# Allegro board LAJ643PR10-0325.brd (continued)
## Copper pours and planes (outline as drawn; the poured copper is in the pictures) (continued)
NVVDD_LG1 on IN3 (solid shape): 225.57,54.58 226.25,54.58 226.79,54.04 226.79,52.64 226.55,52.4 226.11,52.4 225.98,52.52 225.98,52.78 226.17,52.97 226.17,53.6 225.94,53.82 225.6,53.82 225.56,53.86 225.56,54.59
NVVDD_LG1 on IN3: 207.67,59.04 207.03,59.04 206.86,58.87 206.86,58.24 207.83,57.27 208.06,57.27 208.58,57.79 208.58,58.13
NVVDD_LG2 on BOTTOM (solid shape): 199.65,59.9 199.65,57.9 199.57,57.81 199.12,57.81 199.11,57.82 198.49,57.82 198.45,57.86 198.45,59.48 198.46,59.49 198.46,59.98 198.6,60.11 199.44,60.11
NVVDD_LG2 on BOTTOM (solid shape): 227.99,54.33 227.99,53.64 228.62,53.01 228.62,52.8 228.54,52.71 228.33,52.71 228.28,52.77 227.83,52.77 227.72,52.89 227.72,53.54 227.77,53.59 227.77,54.35 227.82,54.4 227.92,54.4
NVVDD_LG2 on IN1 (solid shape): 228.63,53.01 228.63,52.8 228.53,52.7 228.1,52.7 227.49,52.09 227.44,52.09 226.95,52.58 226.95,52.65 227.74,53.44 228.2,53.44
NVVDD_LG2 on IN1: 199.37,58.91 198.94,58.49 198.94,58.15 199.76,57.34 200.09,57.34 200.62,57.87 200.62,57.99 199.69,58.91
NVVDD_LG3 on BOTTOM (solid shape): 219.97,60.83 219.98,60.83 220.11,60.7 220.11,59.5 220.04,59.43 219.93,59.43 219.85,59.51 219.85,60.15 219.63,60.37 218.55,60.37 218.41,60.24 217.49,60.24 216,58.75 215.2,58.75 215.09,58.64 215.09,58.22 214.97,58.1 214.38,58.1 214.32,58.16 214.32,59.86 214.35,59.88 216.05,59.88 217.04,60.88 219.93,60.88
NVVDD_LX1 on BOTTOM (solid shape): 206.05,54.29 206.05,53.18 206.01,53.15 205.16,53.15 205.12,53.18 205.12,54.32 205.16,54.36 205.98,54.36
NVVDD_LX1 on BOTTOM (solid shape): 226,54.34 226,53.62 225.89,53.51 225.89,53.23 225.51,52.85 225.51,52.4 225.46,52.35 224.95,52.35 224.88,52.42 224.88,53.56 225.72,54.4 225.94,54.4
NVVDD_LX1 on IN3 (solid shape): 206.96,53.79 206.96,52.91 206.81,52.76 205.32,52.76 205.17,52.91 205.17,53.77 205.32,53.91 206.85,53.91
NVVDD_LX1 on IN3 (solid shape): 225.95,53.24 225.95,53.18 224.78,52.01 224.63,52.01 224.23,52.41 224.23,52.6 224.48,52.85 224.48,52.86 225.14,53.51 225.67,53.51
NVVDD_LX1_1 on BOTTOM (solid shape): 207.26,63.23 207.26,61.13 207.12,60.98 206,60.98 205.79,60.77 205.79,59.29 205.72,59.22 202.55,59.22 202.5,59.28 202.5,63.21 202.6,63.32 204.38,63.32 204.39,63.3 204.43,63.26 204.43,62.42 204.47,62.39 205.24,62.39 205.3,62.44 205.3,63.24 205.38,63.32 207.17,63.32
NVVDD_LX2 on BOTTOM (solid shape): 197.99,54.25 197.99,53.14 197.95,53.11 197.1,53.11 197.06,53.14 197.06,54.28 197.1,54.32 197.92,54.32
NVVDD_LX2 on BOTTOM (solid shape): 228.51,54.3 228.51,53.91 228.99,53.44 229.3,53.44 229.87,54 230.71,54 231.14,53.57 231.14,53.26 231.01,53.13 230.15,53.13 230.01,52.99 230.01,52.48 229.92,52.4 229.51,52.4 228.28,53.62 228.28,54.32 228.34,54.38 228.43,54.38
NVVDD_LX2 on IN1 (solid shape): 198.93,53.54 198.93,52.91 198.8,52.78 197.09,52.78 196.94,52.93 196.94,53.47 197.07,53.6 197.86,53.6 197.88,53.62 198.85,53.62
NVVDD_LX2 on IN1 (solid shape): 231.7,53.13 231.7,52.25 231.53,52.07 230.97,52.07 230.89,52.14 230.89,52.86 230.33,53.41 230.33,53.95 230.51,54.13 230.71,54.13
NVVDD_LX2_1 on BOTTOM (solid shape): 196.74,63.29 196.74,62.42 196.8,62.36 197.56,62.36 197.62,62.43 197.62,63.25 197.7,63.33 199.35,63.33 199.54,63.14 199.54,61.44 199.11,61.01 198.05,61.01 197.87,60.83 197.87,59.27 197.79,59.19 194.58,59.19 194.53,59.25 194.53,63.02 194.84,63.34 196.7,63.34
NVVDD_LX3 on BOTTOM (solid shape): 213.86,54.29 213.86,53.19 213.83,53.15 212.98,53.15 212.94,53.19 212.94,54.33 212.97,54.36 213.8,54.36
NVVDD_LX3 on BOTTOM (solid shape): 220.1,58 220.1,57.31 220.32,57.09 220.71,57.09 220.85,57.23 221.11,57.23 221.63,56.71 221.63,56.08 221.57,56.02 220.94,56.02 220.86,56.1 220.86,56.38 220.82,56.42 220.29,56.42 220.21,56.49 220.21,56.69 219.86,57.04 219.86,57.99 219.93,58.05 220.05,58.05
NVVDD_LX3_1 on BOTTOM (solid shape): 213.37,63.33 214.29,63.33 214.29,63.33 214.9,63.33 215.13,63.1 215.13,61.59 215.12,61.49 215.13,61.39 215.13,60.87 214.65,60.39 214.14,60.39 214.11,60.37 214.1,60.37 213.9,60.16 213.9,60.15 213.82,60.07 213.82,59.22 210.63,59.22 210.54,59.31 210.54,63.22 210.66,63.33 212.11,63.33 212.2,63.24 212.2,62.41 212.96,62.41 213.03,62.48 213.03,63.35 213.36,63.35
NVVDD_UG1 on BOTTOM (solid shape): 210.04,54.43 210.04,53.12 209.96,53.05 209.14,53.05 209.08,53.11 209.08,54.44 209.13,54.49 209.97,54.49
NVVDD_UG1 on BOTTOM (solid shape): 225.45,55.36 225.45,55.21 225.41,55.17 224.75,55.17 224.18,54.61 224.18,54.51 224,54.32 223.83,54.32 223.69,54.45 223.69,55.06 223.81,55.17 224.17,55.17 224.41,55.41 225.4,55.41
NVVDD_UG1 on IN3 (solid shape): 210.81,53.35 210.81,52.75 210.74,52.68 209.15,52.68 209.02,52.8 209.02,53.32 209.16,53.47 210.69,53.47
NVVDD_UG1 on IN3 (solid shape): 224.54,55.05 224.54,54.89 223.78,54.13 223.49,54.13 223.26,53.91 223.16,53.91 222.75,54.32 222.75,54.55 223.33,55.13 224.1,55.13 224.18,55.2 224.39,55.2
NVVDD_UG1_R on BOTTOM (solid shape): 208.46,54.52 208.46,53.64 208.43,53.62 206.55,53.62 206.41,53.75 206.41,54.3 206.46,54.35 207.6,54.35 207.77,54.53 208.45,54.53
NVVDD_UG2 on BOTTOM (solid shape): 202.17,54.35 202.17,53.1 202.09,53.03 201.27,53.03 201.21,53.09 201.21,54.18 201.21,54.18 201.21,54.42 201.27,54.48 202.04,54.48
NVVDD_UG2 on IN1 (solid shape): 202.19,53.39 202.19,52.01 202.19,52.02 202.19,52.04 202.12,51.97 201.58,51.97 201.07,52.48 201.07,53.33 201.22,53.48 202.11,53.48
NVVDD_UG2 on IN1 (solid shape): 230.76,55.37 230.76,55.04 230.61,54.89 230.33,54.89 229.85,54.4 229.85,53.87 229.77,53.79 229.16,53.79 229.06,53.9 229.06,54.79 229.77,55.5 230.64,55.5
NVVDD_UG2_R on BOTTOM (solid shape): 200.54,54.44 200.54,53.6 200.51,53.57 198.6,53.57 198.46,53.71 198.46,54.26 198.51,54.31 199.65,54.31 199.82,54.48 200.49,54.48
NVVDD_UG3_R on BOTTOM (solid shape): 216.37,54.22 216.37,53.38 216.35,53.36 215.79,53.36 215.52,53.63 214.51,53.63 214.38,53.77 214.38,54.32 214.43,54.37 216.22,54.37
QPCN on TOP (solid shape): 238.59,15.27 238.59,12.14 238.55,12.1 238.45,12.1 238.4,12.15 238.4,13.32 237.66,14.06 237.66,15.26 237.72,15.33 238.54,15.33
QPCP on TOP (solid shape): 239.86,15.22 239.86,13.97 239.77,13.88 239.48,13.88 238.98,13.39 238.98,12.13 238.95,12.1 238.83,12.1 238.8,12.13 238.8,15.18 238.89,15.28 239.8,15.28
SNB_1.35VSDGPUP on BOTTOM (solid shape): 261.85,59.19 261.85,58.51 261.6,58.25 260.92,58.25 260.49,57.82 259,57.82 258.89,57.93 258.89,59.24 258.99,59.34 261.71,59.34
SNB_PH1 on TOP (solid shape): 149.69,126.45 149.69,124.8 149.62,124.74 147.72,124.74 147.66,124.8 147.66,125.44 147.75,125.53 148.44,125.53 148.61,125.7 148.61,126.45 148.67,126.52 149.62,126.52
SNB_PH2 on TOP (solid shape): 143,126.58 144.61,126.58 144.67,126.52 144.67,124.93 144.61,124.86 143.65,124.86 142.38,126.13 142.38,126.26 142.79,126.67 142.91,126.67
SNB_PH3 on BOTTOM (solid shape): 140.54,128.93 140.54,128.36 140.86,128.04 141.43,128.04 141.5,127.98 141.5,126.96 141.37,126.83 139.97,126.83 139.84,126.96 139.84,128.86 139.97,128.99 140.48,128.99
SNB_PH4 on TOP (solid shape): 128.48,129.5 128.48,128.23 128.41,128.17 127.91,128.17 127.87,128.2 127.87,128.7 127.89,128.72 127.89,129.19 127.65,129.44 127.21,129.44 127.14,129.37 127.14,128.74 127.08,128.67 125.43,128.67 125.37,128.74 125.37,129.75 125.56,129.94 128.03,129.94
SPK_L+_CONN on TOP (solid shape): 300.33,45.18 300.33,44.27 298.43,42.37 296.57,42.37 296.45,42.49 296.45,43.25 296.68,43.48 297.21,43.48 297.53,43.48 297.55,43.51 298.13,43.51 299.15,44.53 299.15,45.14 299.46,45.45 300.05,45.45
SPK_L+_CONN on BOTTOM (solid shape): 300.39,44.46 300.22,44.29 299.27,44.29 299.2,44.37 299.2,45.18 299.56,45.54 299.56,46.71 299.58,46.73 300.39,46.73
SPK_L-_CONN on TOP (solid shape): 301.75,44.84 301.75,43.35 298.57,40.17 297.1,40.17 297.04,40.23 297.04,41.35 297.24,41.55 298.44,41.55 300.64,43.75 300.64,44.82 300.8,44.98 301.61,44.98
SPK_L-_CONN on BOTTOM (solid shape): 301.64,45.46 301.74,45.36 301.74,44.36 301.61,44.23 300.87,44.23 300.67,44.43 300.67,45.28 300.82,45.43 300.82,46.73 301.64,46.73
SPK_OUT_L+ on TOP (solid shape): 291.19,21.54 292.36,21.54 292.41,21.49 292.41,21.38 292.36,21.33 291.22,21.33 291.04,21.16 290.3,21.16 290.15,21.31 290.15,21.46 290.3,21.61 291.11,21.61
SPK_OUT_L+ on TOP (solid shape): 292.56,43.49 292.56,42.45 292.44,42.34 290.24,42.34 290.24,42.34 290.17,42.34 290.04,42.48 290.04,43.46 290.19,43.62 292.43,43.62
SPK_OUT_L+ on IN3 (solid shape): 292.98,43.42 292.98,42.62 292.88,42.51 290.68,42.51 290.42,42.77 290.42,43.39 290.62,43.58 292.82,43.58
SPK_OUT_L+ on IN3 (solid shape): 289.13,22.14 289.74,22.14 289.97,21.9 291.31,21.9 291.42,21.79 291.42,21.47 291.21,21.26 290.21,21.26 290.1,21.37 288.39,21.37 288.16,21.6 288.16,22.02 288.28,22.15 289.12,22.15
SPK_OUT_L- on TOP (solid shape): 292.56,41.63 292.56,40.64 292.38,40.46 290.23,40.46 290.04,40.65 290.04,41.58 290.2,41.74 292.45,41.74
SPK_OUT_L- on TOP (solid shape): 292.41,21.08 292.41,20.98 292.37,20.94 291.2,20.94 290.78,20.52 290.02,20.52 289.92,20.62 289.92,20.9 290.05,21.03 291.08,21.03 291.18,21.13 292.36,21.13
SPK_OUT_L- on IN3 (solid shape): 292.87,40.56 292.87,40.46 292.28,39.87 291.66,39.87 290.47,41.06 290.47,41.3 291.09,41.92 291.51,41.92
SPK_OUT_L- on IN3 (solid shape): 288.17,21.23 288.28,21.12 288.58,21.11 288.7,21.12 289.99,21.12 290.11,21.01 291.12,21.01 291.2,20.93 291.2,20.59 291.13,20.51 289.19,20.51 288.92,20.23 287.52,20.23 287.01,20.74 287.01,20.75 287.01,20.99 287.26,21.24 288.15,21.24
SPK_OUT_R+ on TOP (solid shape): 292.56,39.6 292.56,38.61 292.47,38.52 290.66,38.52 290.33,38.85 290.33,39.54 290.56,39.77 292.4,39.77
SPK_OUT_R+ on TOP (solid shape): 292.41,20.29 292.41,20.19 292.36,20.14 291.55,20.14 290.72,19.31 290.72,19.01 290.58,18.87 289.69,18.87 289.59,18.97 289.59,19.43 289.74,19.58 290.68,19.58 291.43,20.33 292.38,20.33
SPK_OUT_R+ on IN3 (solid shape): 290.68,19.36 290.68,18.09 289.82,17.22 288.48,17.22 288.21,17.49 288.21,18.03 289.28,19.1 289.28,19.25 289.51,19.47 290.56,19.47
SPK_OUT_R+ on IN3 (solid shape): 291.6,39.57 291.6,39.2 291.47,39.07 290.65,39.07 289.81,39.92 289.44,39.92 289.34,40.02 289.34,40.92 289.42,41.01 290.16,41.01
SPK_OUT_R- on TOP (solid shape): 289.98,39.53 289.98,38.67 290.74,37.92 292.43,37.92 292.56,37.79 292.56,36.8 292.48,36.72 290.21,36.72 288.78,38.16 288.78,39.59 288.9,39.71 289.8,39.71
SPK_OUT_R- on TOP (solid shape): 292.41,20.67 292.41,20.6 292.36,20.54 291.39,20.54 290.58,19.73 289.79,19.73 289.72,19.81 289.72,20.24 289.82,20.34 290.86,20.34 291.25,20.73 292.35,20.73
SPK_OUT_R- on IN3 (solid shape): 289.91,39.4 289.91,39.11 288.76,37.97 288.64,37.97 288.09,38.52 288.09,38.8 288.87,39.58 289.73,39.58
SPK_OUT_R- on IN3 (solid shape): 290.93,19.98 290.67,19.73 289.4,19.73 288.39,18.71 287.62,18.71 287.62,19.6 287.91,19.88 288.93,19.88 289.3,20.26 290.93,20.26
SPK_R+_CONN on TOP (solid shape): 303.17,44.85 303.17,43.63 302.95,43.42 302.21,43.42 302.07,43.55 302.07,44.83 302.2,44.95 303.07,44.95
SPK_R+_CONN on TOP (solid shape): 300.24,40.04 300.24,39.69 298.85,38.29 297.36,38.29 297.08,38.57 297.08,39.35 297.31,39.57 298.45,39.57 299.49,40.62 299.67,40.62
SPK_R+_CONN on BOTTOM (solid shape): 303.08,46.66 303.08,44.39 302.93,44.25 302.23,44.25 302.06,44.41 302.06,46.63 302.17,46.73 303.01,46.73
SPK_R-_CONN on TOP (solid shape): 304.66,44.79 304.66,43.64 304.5,43.49 303.65,43.49 303.5,43.64 303.5,44.83 303.64,44.97 304.48,44.97
SPK_R-_CONN on TOP (solid shape): 300.39,37.89 300.39,37.62 299.13,36.36 297.25,36.36 297.08,36.52 297.08,37.21 297.29,37.42 298.66,37.42 299.67,38.43 299.85,38.43
SPK_R-_CONN on BOTTOM (solid shape): 304.37,46.63 304.37,45.66 304.56,45.47 304.56,44.52 304.41,44.38 303.55,44.38 303.33,44.6 303.33,46.64 303.42,46.73 304.27,46.73
SPOK# on TOP (solid shape): 17.61,80.54 17.61,78.51 17.48,78.38 17.1,78.38 16.97,78.51 16.97,79.4 16.85,79.53 16.59,79.53 16.46,79.65 16.46,80.54 16.59,80.67 17.48,80.67
UG_DDR on TOP (solid shape): 94.19,33.3 94.19,32.41 94.06,32.28 93.17,32.28 93.05,32.41 93.05,33.17 93.3,33.42 94.06,33.42
N15156561 on BOTTOM (solid shape): 221.1,61.28 221.1,60.73 221.25,60.58 222.48,60.58 222.65,60.41 222.65,59.92 222.55,59.81 220.93,59.81 220.55,59.44 220.45,59.44 220.45,59.44 220.37,59.53 220.37,60.65 220.48,60.76 220.48,61.38 220.51,61.4 220.98,61.4
N17572010 on BOTTOM (solid shape): 240.42,49.72 240.42,48.75 240.38,48.71 238.47,48.71 238.38,48.79 238.38,49.65 238.5,49.77 240.37,49.77
N20648577 on BOTTOM (solid shape): 236.71,26.71 236.71,26.64 236.65,26.58 235.87,26.58 235.84,26.54 235.84,26.38 235.85,26.36 236.65,26.36 236.69,26.32 236.69,26.22 236.63,26.16 236.5,26.16 236.44,26.09 236.43,26.09 236.07,25.74 236.07,24.69 236.26,24.5 236.26,24.03 236.24,24.01 235.25,24.01 235.16,24.1 235.16,26.36 235.57,26.77 235.64,26.81 236.6,26.81
N23332881 on TOP (solid shape): outline of 81 points within 274.07,13.12 276.54,18.85
N23332897 on TOP (solid shape): 272.25,15.31 273.46,15.31 273.55,15.23 273.55,14.69 273.47,14.62 270.82,14.62 270.64,14.79 270.64,15.69 270.74,15.79 271.77,15.79
N23332925 on TOP (solid shape): 276.5,12.3 276.5,10.13 276.25,9.88 274.7,9.88 274.63,9.94 274.63,12.42 274.75,12.55 276.25,12.55
N27740851 on TOP (solid shape): 45.95,43.26 45.95,43.25 46.04,43.17 46.04,39.54 45.98,39.48 45.9,39.48 45.84,39.54 45.84,40.62 45.76,40.69 44.54,40.69 44.44,40.59 44.44,39.53 44.39,39.48 44.25,39.48 44.15,39.58 44.15,40.7 44.21,40.76 44.21,43.05 44.09,43.16 43.05,43.16 42.99,43.22 42.99,43.3 43.05,43.36 43.84,43.36 43.84,43.36 45.85,43.36
N27740851 on BOTTOM (solid shape): 46.06,43.22 46.06,41.01 45.72,40.66 44.46,40.66 44.22,40.9 44.22,43.25 44.35,43.38 45.91,43.38
N27801570 on TOP (solid shape): 44.38,47.43 44.43,47.38 44.43,46.4 44.57,46.26 45.7,46.26 45.85,46.4 45.85,47.37 45.88,47.41 46.01,47.41 46.04,47.37 46.04,46.2 45.95,46.11 45.95,43.6 45.91,43.56 43.03,43.56 42.99,43.6 42.99,43.72 43.03,43.76 44.04,43.76 44.19,43.91 44.19,47.37 44.26,47.44 44.38,47.44
N27801570 on BOTTOM (solid shape): 46.08,46.06 46.08,43.66 45.99,43.57 44.28,43.57 44.18,43.68 44.18,46.1 44.26,46.19 45.96,46.19
N80922351 on BOTTOM (solid shape): 173.74,103.07 173.74,102.66 175.21,101.19 175.21,100.94 173.92,99.64 173.11,99.64 173.01,99.72 172.9,99.76 172.88,99.77 171.3,101.34 171.3,101.85 171.46,102.01 171.47,101.99 171.8,102.32 172.19,101.93 172.22,101.93 172.57,102.28 172.57,102.31 172.19,102.69 172.19,102.71 172.35,102.87 172.39,102.87 172.78,102.49 173.13,102.84 173.13,102.87 172.74,103.26 173.01,103.53 173.28,103.53
N100118189 on TOP (solid shape): 40.07,34.96 40.07,26.22 39.91,26.06 38.44,26.06 38.31,26.19 38.31,35.84 38.44,35.96 39.07,35.96

Small or netless copper shapes (teardrops, artwork), in the pictures only: 140 on TOP, 48 on BOTTOM, 34 on IN2

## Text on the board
User.Comments: LA-J643P | 2020-12-06 | 2019-12-06 | GPC52 | crazy | REV:0.3
BODY_CENTER: 313.60 | 134.42 | 3.40 | TOP
COMPVAL_TYPE_BOTTOM: TOP LIMIT
COMPVAL_TYPE_TOP: 5.80 | 2.80 | 0.00 | 120.00 | n | 4.10 | 5.50 | 7.20 | 4.00 | 2.30 | 4.30 | 5.30 | 157.60 | 1.00 | 5.90 | 2.40 | 6.00 | TOP PAD
USER_PART_NUM_TOP: 85.30 | 0.00 | 35.34 | 110.00 | 116.85 | 120.88 | 145.40 | 146.45 | 149.58 | 128.50 | 111.52 | 113.25 | 134.30 | 142.95 | 147.48 | 151.00 | 112.81 | 167.75 | 135.67 | 96.95 | 73.22 | 94.50 | 126.24 | 131.18 | 141.65 | 74.98 | 2.15 | 39.40 | 73.65 | 110.75 | 125.33 | BOT
DEVICE_TYPE_TOP: BOT LIMIT
PAGE_OUTLINE: 149.00 | 30.00 | 36.80 | 0.00 | 96.00 | 104.00 | 120.00 | 1.000 | SCALE | 5.50 | n | 177.50 | 170.00 | 165.00 | 157.00 | 132.70 | 124.40 | 1.00 | 4.00 | BOT PAD
User.7: 0.00 | 21.08 | 50.01 | 111.00 | 155.50 | 50.25 | 43.62 | 30.00 | 41.12 | 63.25 | 64.01 | 72.00 | 76.00 | 150.10 | 158.90 | TOP
User.32: SILKSCREEN_BOTTOM
User.45: Excess check:Oct 12 16:27:34 2018 | PadStack_Check:Oct 12 16:22:17 2018 | XY-Check acute:Oct 11 20:29:10 2018 | XY-Check rotation:Oct 12 16:18:12 2018 | XY-Check txt overlap:Oct 12 16:15:26 2018 | XY-Create nettxt:Oct 09 13:20:50 2018 | XY-Create plane:Oct 11 17:07:51 2018 | XY-Excess check:Oct 12 16:27:34 2018 | XY-Mask check:Oct 12 16:24:43 2018 | XY-Outline check:Oct 12 16:33:23 2018 | XY-PadStack_Check:Oct 12 16:22:17 2018 | XY-Plane net check:Oct 12 16:30:19 2018 | XY-bbvia check:Oct 12 16:23:15 2018 | XY-shape pin check:Oct 12 16:26:13 2018 | XY-via check:Oct 12 16:22:27 2018 | bbvia check:Oct 12 16:23:15 2018 | check rotation:Oct 12 16:18:12 2018 | check txt overlap:Oct 12 16:15:26 2018 | create nettxt:Oct 09 13:20:50 2018 | create plane:Oct 09 19:47:52 2018 | outline check:Oct 12 16:33:23 2018 | plane net check:Oct 12 16:30:19 2018 | shape pin check:Oct 12 16:26:13 2018 | via check:Oct 12 16:22:27 2018 | 7.7 | 8.5 | 8 | 6 | 5 | 5.2/4.4 | 6/5.5 | 5.3/5.7 | 5/5.1 | 5/5.5 | 5/6 | 5.3/8.7 | 5/7.5 | 4/8 | trace Width | 6.1 | 5.5/4.5 | Width/Space | L2/L4 | L4/L7 | ref | L2 | L7 | 45 ohm | 80 ohm | L5/L7 | HR_1_4mm-6L and 8L and 10L(5mil 50 ohm)_170823 | FIGURE | SIZE | 8.0 | 10.0 | 18.0 | 22.0 | 31.0 | 35.0 | 39.0 | 91.0 | 94.0 | 157.0 | 161.0 | 28.0 | 43.0 | 63.0 | 35.0x16.0 | 39.0x20.0 | 63.0x20.0 | 63.0x24.0 | 63.0x35.0 | 71.0x31.0 | 75.0x24.0 | 94.0x31.0 | 110.0x91.0 | 33.0x28.0 | DRILL CHART: TOP to BOTTOM | ALL UNITS ARE IN MILS | TOLERANCE | +3.0/-3.0 | +2.0/-2.0 | PLATED | NON-PLATED | QTY | 8274 | 69 | 10 | 19 | 9 | 20 | 11 | 1 | 7 | 4 | 2
